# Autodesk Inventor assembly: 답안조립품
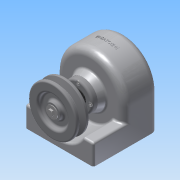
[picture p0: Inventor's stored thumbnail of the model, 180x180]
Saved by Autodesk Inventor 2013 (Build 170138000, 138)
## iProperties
Created: 2015-02
Part Number: 답안조립품
Document SubType Name: Assembly
Designer: Administrator
Author: Administrator
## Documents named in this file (14)
- C:\Documents and Settings\Administrator\바탕 화면\450214V1017\답안조립품.iam
- C:\Documents and Settings\Administrator\바탕 화면\450214V1017\1-본체.ipt
- C:\Documents and Settings\Administrator\바탕 화면\450214V1017\베어링 6001.ipt
- C:\Documents and Settings\Administrator\바탕 화면\450214V1017\키5x5.ipt
- C:\Documents and Settings\Administrator\바탕 화면\450214V1017\축.ipt
- C:\Documents and Settings\Administrator\바탕 화면\450214V1017\5-스퍼기어.ipt
- C:\Documents and Settings\Administrator\바탕 화면\450214V1017\오일실.ipt
- C:\Documents and Settings\Administrator\바탕 화면\450214V1017\축커버.ipt
- C:\Documents and Settings\Administrator\바탕 화면\450214V1017\M3x0.5.ipt
- C:\Documents and Settings\Administrator\바탕 화면\450214V1017\키4x4.ipt
- C:\Documents and Settings\Administrator\바탕 화면\450214V1017\4-V-벨트풀리.ipt
- C:\Documents and Settings\Administrator\바탕 화면\450214V1017\M5x0.8.ipt
- M5x0.8.ipt
- C:\Documents and Settings\Administrator\바탕 화면\450214V1017\와샤.ipt
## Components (7 placed, 4 different names)
1. 1-본체:1
2. 4-V-벨트풀리:1 — 각도:4
3. M5x0.8:1 — 각도:5
4. M3x0.5:1
5. M3x0.5:2
6. M3x0.5:3
7. M3x0.5:4
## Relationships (2: Angle 2)
- 각도:4 [Angle]: 4-V-벨트풀리:1
- 각도:5 [Angle]: M5x0.8:1
